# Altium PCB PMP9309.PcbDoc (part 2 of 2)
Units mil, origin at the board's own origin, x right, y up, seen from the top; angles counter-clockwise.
Board outline 7000 x 6500 mil, 4 copper layers (Top Layer, MidLayer1, MidLayer2, Bottom Layer), stack 90 mil thick; 176 components, 71 nets, 1187 pads, 29 vias.
Unrouted connection lines stored in the file: 1.
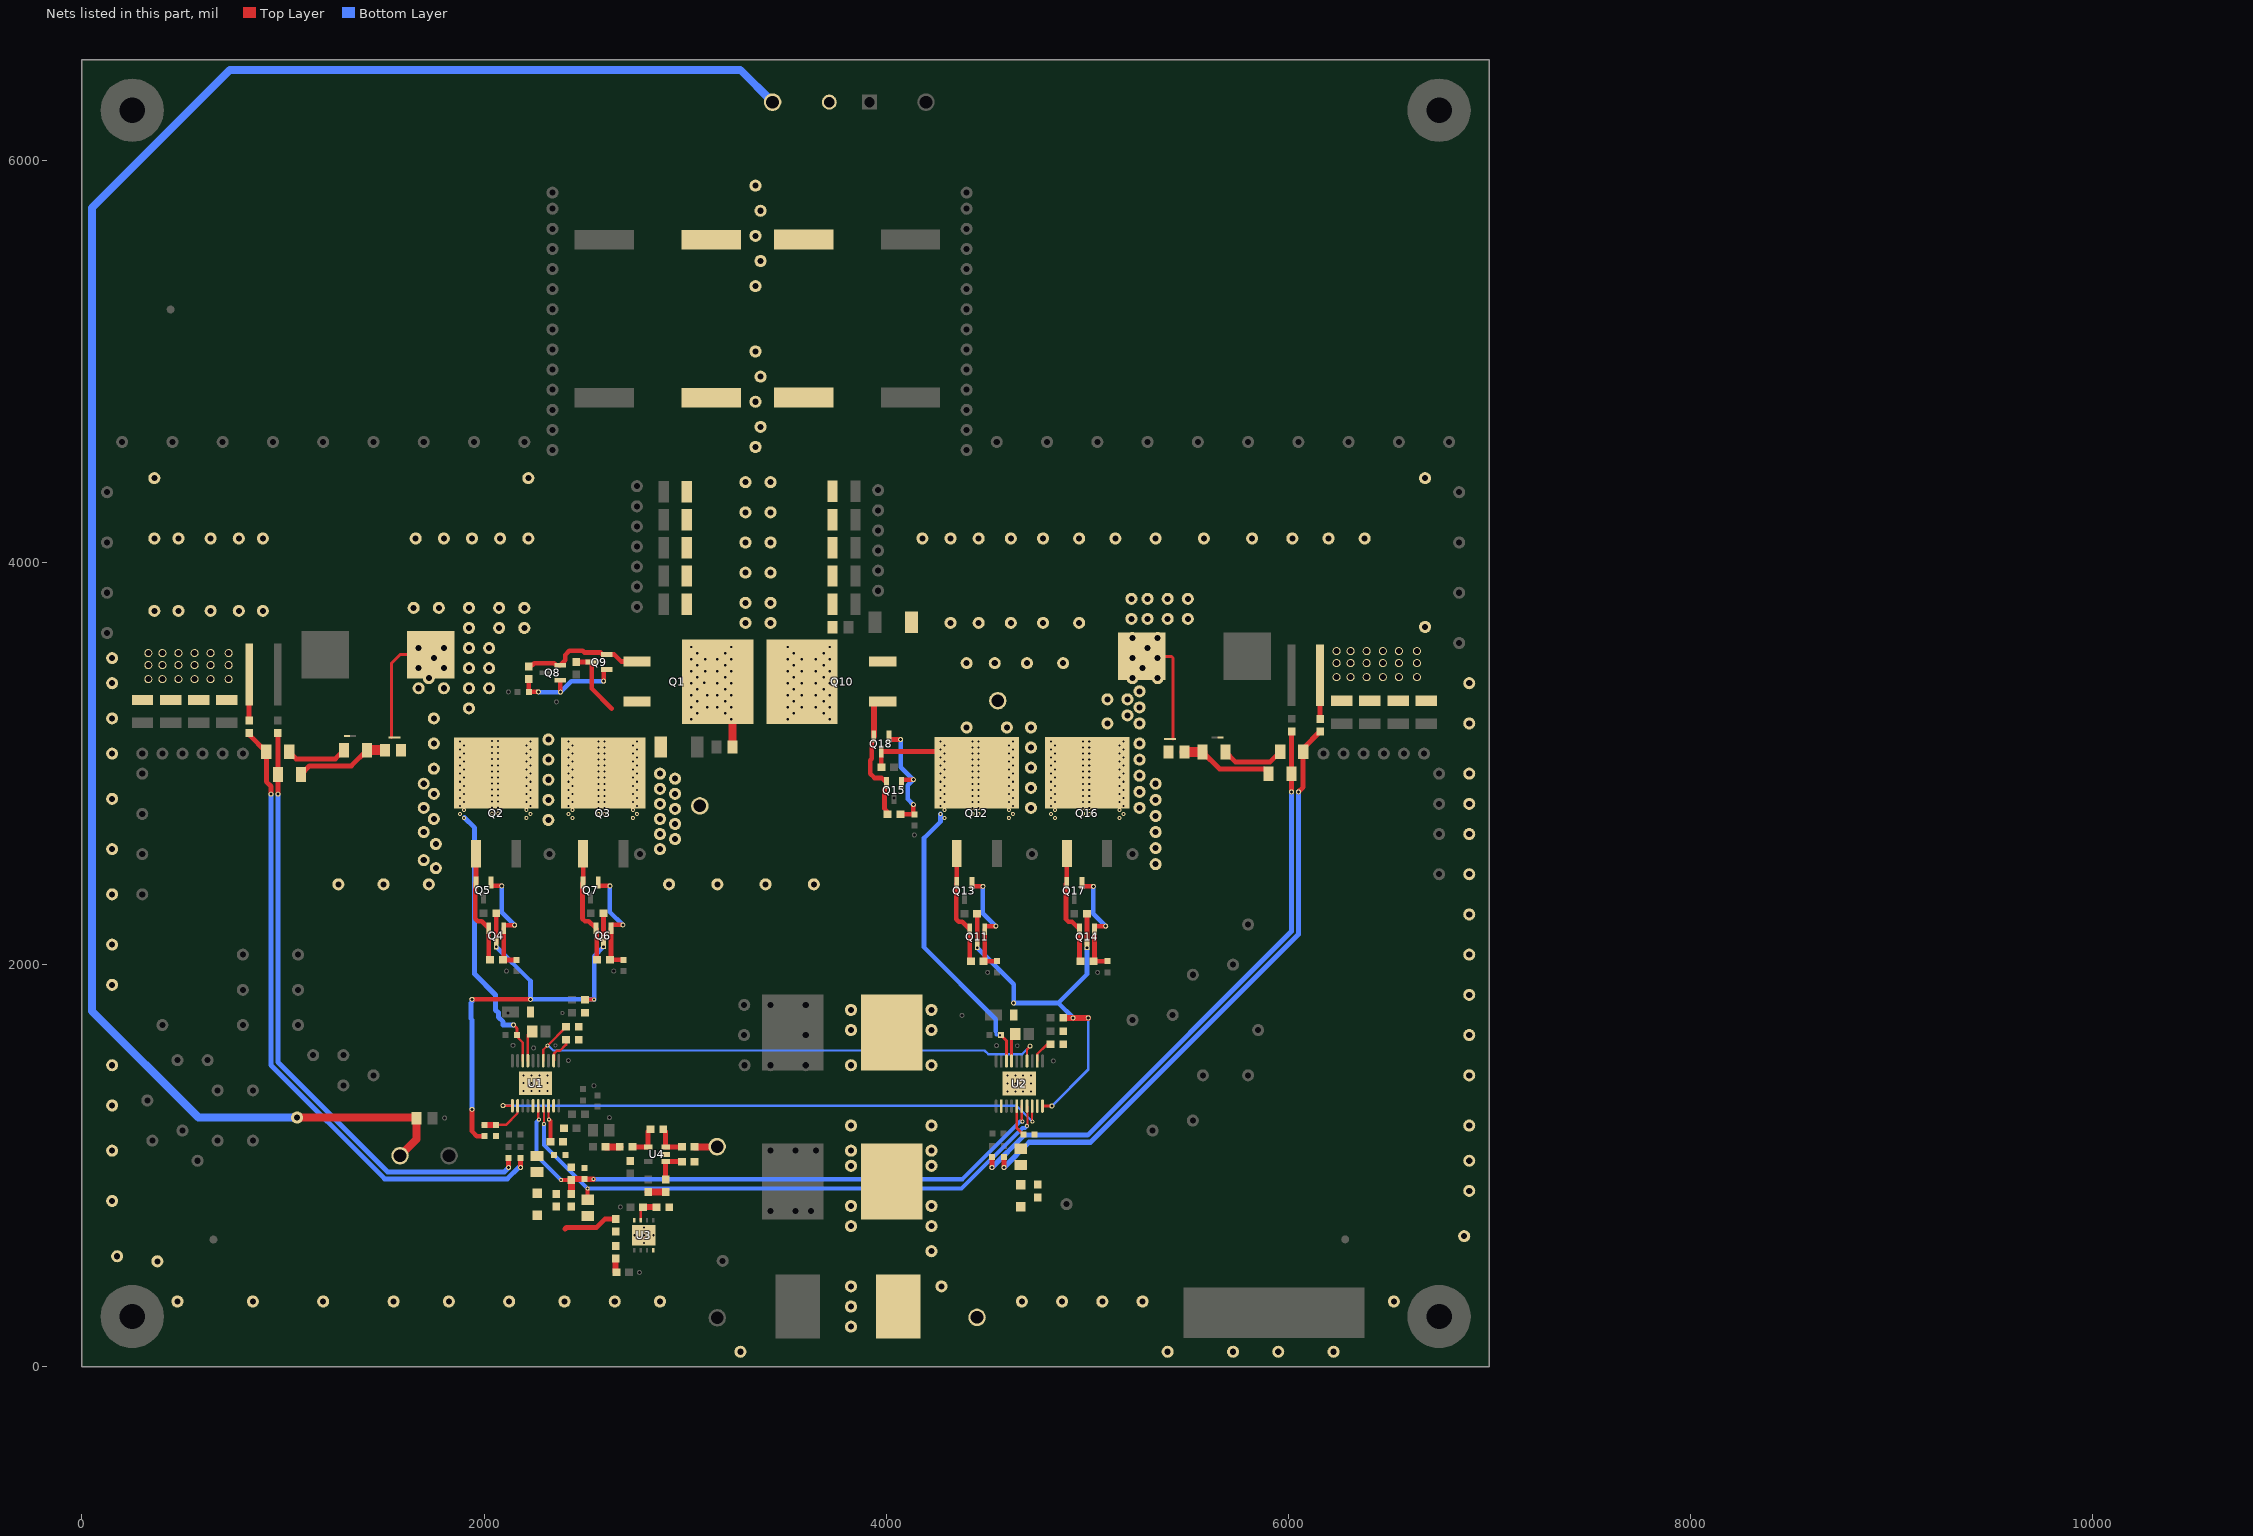
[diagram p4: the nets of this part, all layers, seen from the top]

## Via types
v1: diameter 20, hole 10, Top Layer to Bottom Layer, 29 vias

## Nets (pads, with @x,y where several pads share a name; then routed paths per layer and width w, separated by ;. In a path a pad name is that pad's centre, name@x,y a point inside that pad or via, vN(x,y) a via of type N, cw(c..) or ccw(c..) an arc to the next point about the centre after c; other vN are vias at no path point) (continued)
NetC41_1: C41.1 R39.1 R54.2 | length 467.5
  Top Layer w25: R54.2@1089.07,2946.35 1131.72,2989 1339.68,2989 C41.1@1417.68,3067
  Top Layer w50: C41.1@1417.68,3067 R39.1@1506.59,3067
NetC41_2: C41.2 NT3.1 R53.2 | length 304.5
  Top Layer w25: R53.2@1031.07,3058.35 1065.43,3024 1260.5,3024 C41.2@1303.5,3067
NetC42_1: C42.1 R55.1 R59.2 | length 462
  Top Layer w25: C42.1@5573.6,3058 5657.68,2973.92 5878,2973.92 R59.2@5901.91,2950
  Top Layer w50: R55.1@5484.68,3058 C42.1@5573.6,3058
NetC42_2: C42.2 NT5.1 R58.2 | length 313.2
  Top Layer w25: C42.2@5687.77,3058 5736.85,3008.92 5909.83,3008.92 R58.2@5959.91,3059
NetC51_1: C51.1 R41.1 | length 65
  Top Layer w30: R41.1@2654.52,472.94 C51.1@2654.52,537.94
NetNT4_1: NT4.1 R39.2
NetNT6_1: NT6.1 R55.2
NetQ1_1: Q1.1 Q8.2 Q9.2 R24.2 | length 614.8
  Top Layer w23: R24.2@2222.56,3483.94 2228.46,3489.84 2240.11,3489.84 2250.02,3499.75 2348.39,3499.75 2358.3,3489.84 Q8.2@2378.96,3489.84 2403.36,3514.24 2403.36,3540.33 2424.15,3561.12 2490.96,3561.12 2499.33,3552.75 2579.39,3552.75 2589.3,3542.84 Q9.2@2609.96,3542.84 2647.16,3542.84 2682,3508 Q1.1@2759.94,3508
NetQ2_1: Q2.1 Q4.2 Q5.2 R22.2 | length 561.3
  Top Layer w23: Q2.1@1959.6,2551.54 Q5.2@1959.6,2408.4 1956.32,2405.12 1956.32,2229.39 1968.91,2216.8 1987.89,2216.8 Q4.2@2023.6,2181.09 R22.2@2023.6,2030.59
NetQ3_1: Q3.1 Q6.2 Q7.2 R23.2 | length 567.9
  Top Layer w23: Q3.1@2492.6,2551.54 Q7.2@2492.6,2408.4 2489.32,2405.12 2489.32,2229.39 2501.91,2216.8 2521.2,2216.8 Q6.2@2556.6,2181.4 2560.69,2177.31 R23.2@2560.69,2025.82
NetQ4_1: pad.0@2088,2392 pad.0@2152,2196.69 Q4.1 Q5.1 R7.2 R22.1 | length 533.8
  Top Layer w23: Q5.1@2043,2392 pad.0@2088,2392 ; R22.1@2093.5,2023.69 R7.2@2161,2023.69 ; R22.1@2098.4,2028.59 Q4.1@2098.4,2181.09 ; Q4.1@2105,2196.69 pad.0@2152,2196.69
  Bottom Layer w23: pad.0@2088,2392 2088,2260.69 pad.0@2152,2196.69
NetQ6_1: pad.0@2626,2392 pad.0@2690,2198 Q6.1 Q7.1 R9.1 R23.1 | length 532.7
  Top Layer w23: Q7.1@2573,2392 pad.0@2626,2392 ; R23.1@2631.4,2029.91 Q6.1@2631.4,2181.4 ; R23.1@2637.31,2024 R9.1@2693,2024 ; Q6.1@2638,2198 pad.0@2690,2198
  Bottom Layer w23: pad.0@2626,2392 2626,2262 pad.0@2690,2198
NetQ8_1: pad.0@2269.56,3357.44 pad.0@2379.56,3355.44 pad.0@2594.56,3410.44 Q8.1 Q9.1 R5.1 R24.1 | length 565.4
  Top Layer w23: R5.1@2223,3357 R24.1@2223,3420.5 ; R5.1@2223.44,3357.44 pad.0@2269.56,3357.44 ; pad.0@2378.96,3356.04 Q8.1@2378.96,3415.04 ; pad.0@2594.56,3410.44 Q9.1@2594.56,3461.44
  Bottom Layer w23: pad.0@2271.56,3355.44 pad.0@2379.56,3355.44 2434.56,3410.44 pad.0@2594.56,3410.44
NetQ10_1: Q10.1 Q15.2 Q18.2 R33.2 | length 620.6
  Top Layer w23: Q18.2@3938.6,3135.4 3938.6,3114.74 3928.69,3104.83 3928.69,3023.78 3921.32,3016.41 3921.32,2949.59 3942.11,2928.8 3977.2,2928.8 Q15.2@4001.6,2904.4 4001.6,2883.74 3991.69,2873.83 3991.69,2775.46 4001.6,2765.55 4001.6,2753.91 R33.2@4007.5,2748
  Top Layer w30: Q18.2@3938.6,3135.4 Q10.1@3938.6,3297
NetQ11_1: pad.0@4481,2390 pad.0@4545,2191.98 Q11.1 Q13.1 R27.1 R30.2 | length 544.5
  Top Layer w23: Q13.1@4432,2390 pad.0@4481,2390 ; R27.1@4484.5,2017.98 R30.2@4552,2017.98 ; R27.1@4490.4,2023.89 Q11.1@4490.4,2176.39 ; Q11.1@4494,2191.98 pad.0@4545,2191.98
  Bottom Layer w23: pad.0@4481,2390 4481,2255.99 pad.0@4545,2191.98
NetQ11_2: Q11.2 Q12.1 Q13.2 R27.2 | length 567.8
  Top Layer w23: Q12.1@4351.6,2552.34 Q13.2@4351.6,2406.4 4348.32,2403.12 4348.32,2226.39 4360.91,2213.8 4378.19,2213.8 Q11.2@4415.6,2176.39 R27.2@4415.6,2023.89
NetQ14_1: pad.0@5030,2390 pad.0@5092,2192 Q14.1 Q17.1 R31.1 R32.1 | length 547.7
  Top Layer w23: Q17.1@4978,2390 pad.0@5030,2390 ; R31.1@5030.5,2018 R32.1@5100,2018 ; R31.1@5036.4,2023.91 Q14.1@5036.4,2176.4 ; Q14.1@5042,2192 pad.0@5092,2192
  Bottom Layer w23: pad.0@5030,2390 5030,2254 pad.0@5092,2192
NetQ14_2: Q14.2 Q16.1 Q17.2 R31.2 | length 568.4
  Top Layer w23: Q16.1@4898.6,2552.54 Q17.2@4898.6,2406.4 4894.32,2402.12 4894.32,2226.39 4906.91,2213.8 4924.2,2213.8 Q14.2@4961.6,2176.4 R31.2@4961.6,2023.91
NetQ15_1: pad.0@4072,3120 pad.0@4135,2796 pad.0@4135,2920 Q15.1 Q18.1 R33.1 R35.1 | length 608.1
  Top Layer w23: Q18.1@4020,3120 pad.0@4072,3120 ; R33.1@4070.5,2748 R33.1@4076.4,2753.91 ; Q15.1@4076.4,2883.74 Q15.1@4076.4,2904.4 ; Q15.1@4082,2920 pad.0@4135,2920 ; R33.1@4082.31,2748 R35.1@4140,2748 ; R35.1@4135,2753 pad.0@4135,2796
  Bottom Layer w23: pad.0@4072,3120 4072,2983 pad.0@4135,2920 4106.88,2891.88 4106.88,2824.12 pad.0@4135,2796
NetR3_2: pad.1@2182.37,991.18 pad.3@940,2848 R3.2 R51.1 R53.1 | length 3234.4
  Top Layer w25: R51.1@831.99,3143.27 R53.1@916.9,3058.35 916.9,2910.1 940,2887 pad.3@940,2848 ; pad.1@2182.37,991.18 R3.2@2182.37,1038.18
  Bottom Layer w25: pad.3@940,2848 940,1500.5 1505.5,935 2115.68,935 2171.86,991.18 pad.1@2182.37,991.18
NetR4_2: pad.0@2122.37,991.18 pad.3@975,2848 R4.2 R52.1 R54.1 | length 3064.7
  Top Layer w25: R54.1@973.99,2947.27 R52.1@973.99,3151.86 ; pad.3@975,2848 R54.1@975,2946.26 ; pad.0@2122.37,991.18 R4.2@2122.37,1038.18
  Bottom Layer w25: pad.3@975,2848 975,1515 1520,970 2101.18,970 pad.0@2122.37,991.18
NetR28_2: pad.3@4586,991.68 pad.3@6051,2860 R28.2 R56.1 R58.1 | length 3048.4
  Top Layer w25: pad.3@4586.18,991.85 R28.2@4586.18,1042.5 ; pad.3@6051,2860 6074.09,2883.09 R58.1@6074.09,3059 6074.09,3075.59 R56.1@6158,3159.5
  Bottom Layer w25: pad.3@4586,991.68 4711.32,1117 5016.5,1117 6051,2151.5 pad.3@6051,2860
NetR29_2: pad.2@4526,991.68 pad.3@6016,2860 R29.2 R57.1 R59.1 | length 3021.4
  Top Layer w25: pad.2@4526.18,991.85 R29.2@4526.18,1042.5 ; pad.3@6016,2860 R59.1@6016,2949.91 ; R59.1@6016,2950.09 R57.1@6016,3160.5
  Bottom Layer w25: pad.2@4526,991.68 4686.32,1152 5002,1152 6016,2166 pad.3@6016,2860
NetR42_1: R42.1 R43.2 U3.7 | length 120
  Top Layer w12: U3.7@2778.78,729.23 R42.1@2778.78,782.19
  Top Layer w30: R42.1@2791.02,794.43 R43.2@2858.03,794.43
NetR44_2: R44.2 R45.1 U4.1 | length 168
  Top Layer w25: R45.1@2903.52,932.61 U4.1@2903.52,1020.12 R44.2@2984.03,1020.12
NetR45_2: R45.2 R46.1 | length 87
  Top Layer w35: R46.1@2816.52,869.62 R45.2@2903.52,869.62
NetR47_1: R47.1 R50.2 U4.4 | length 171.3
  Top Layer w25: R47.1@2738.02,1094.12 U4.4@2816.52,1094.12 2816.52,1170.61 R50.2@2828.03,1182.12
NetR47_2: R47.2 R48.1 | length 70
  Top Layer w35: R48.1@2605.02,1094.12 R47.2@2675.03,1094.12
NetR49_1: R49.1 TP14.1 | length 112
  Top Layer w35: R49.1@3047.02,1094.12 TP14.1@3159.04,1094.12
NetR49_2: R49.2 R50.1 U4.3 | length 173.7
  Top Layer w25: R50.1@2891.02,1182.12 2903.52,1169.61 U4.3@2903.52,1094.12 R49.2@2984.03,1094.12
OPT1: R6.1 R8.2 U1.2 | length 226.3
  Top Layer w12: R8.2@2060.52,1203.12 2108.52,1203.12 2166.52,1261.12 2166.52,1298.07 U1.2@2166.75,1298.3
  Top Layer w30: R6.1@2001.52,1203.12 R8.2@2060.52,1203.12
RES: C19.1 pad.0@2315,1597.08 pad.0@4716,1594.68 U1.14 U2.14 | length 2729
  Top Layer w12: U1.14@2294.7,1522.71 2294.7,1576.78 pad.0@2315,1597.08 C19.1@2408.03,1690.11 ; U2.14@4700.39,1521.2 4700.39,1579.07 pad.0@4716,1594.68
  Bottom Layer w12: pad.0@2315,1597.08 2319.79,1597.08 2343.75,1573.12 4489.5,1573.12 4507.43,1555.18 4676.5,1555.18 pad.0@4716,1594.68
SGND: C19.2 C20.2 C21.2 C22.2 C49.2 C50.2 C51.2 C52.2 R8.1 R13.1 R15.1 R16.1 R17.1 R19.2 R37.1 R40.1 R43.1 R44.1 U1.9 U1.21 U2.2 U2.9 U2.21 U3.4 U3.9 U4.2
  other v1: 2794.52,615.06 2747.28,654.43 2794.52,654.43 2841.77,654.43 2794.52,693.8 4602.95,1369.63 4642.32,1369.63 4681.69,1369.63 4721.06,1369.63 2197.26,1371.13 2236.63,1371.13 2276,1371.13 2315.37,1371.13 4602.95,1409 4642.32,1409 4681.69,1409 4721.06,1409 2197.26,1410.5 2236.63,1410.5 2276,1410.5 2315.37,1410.5 4602.95,1448.37 4642.32,1448.37 4681.69,1448.37 4721.06,1448.37 2197.26,1449.87 2236.63,1449.87 2276,1449.87 2315.37,1449.87
SLOPE1: R13.2 U1.12 | length 172.8
  Top Layer w12: U1.12@2345.88,1556.06 U1.12@2345.88,1522.71 2348.58,1525.41 2348.58,1558.76 2361.99,1572.17 2377.85,1572.17 2408.03,1602.35 R13.2@2408.03,1627.12
SLOPE2: R37.2 U2.12 | length 120
  Top Layer w12: U2.12@4751.57,1521.2 4751.57,1555.25 4800,1603.68 R37.2@4817.51,1603.68
SS: C22.1 pad.0@2297.32,1207.5 pad.0@2515,886 pad.1@4700,1199 U1.7 U2.7 | length 2966.7
  Top Layer w10: U1.7@2294.7,1298.3 2297.32,1295.68 pad.0@2297.32,1210.5 ; U2.7@4700.39,1296.79 4702,1295.18 pad.1@4702,1201
  Top Layer w20: C22.1@2515,831 pad.0@2515,886
  Bottom Layer w20: pad.0@2297.32,1207.5 2297.32,1103.68 pad.0@2515,886 4374.36,886 4677.36,1189 4689.43,1189 4699.43,1199 pad.1@4700,1199
SW1: C15.1 C27.2 L1.2 NT4.2 pad.0@360,3760 pad.0@360,4420 pad.0@1275,2400 pad.0@1650,3775 pad.0@1880,3110 pad.0@2146,1701 pad.0@2230,3110 pad.0@2440,2730 pad.0@2740,2730 pad.1@360,4120 pad.1@480,3760 pad.1@1500,2400 pad.1@1775,3775 pad.1@1900,3090 pad.1@2210,3090 pad.1@2420,2750 pad.1@2760,2750 pad.2@480,4120 pad.2@640,3760 pad.2@1725,2400 pad.2@1880,3070 pad.2@1925,3775 pad.2@2230,3070 pad.2@2440,2770 pad.2@2740,2770 pad.3@640,4120 pad.3@780,3760 pad.3@1750,3100 pad.3@1900,3050 pad.3@2075,3775 pad.3@2210,3050 pad.3@2420,2790 pad.3@2760,2790 pad.4@780,4120 pad.4@900,3760 pad.4@1750,2975 pad.4@1880,3030 pad.4@2200,3775 pad.4@2230,3030 pad.4@2440,2810 pad.4@2740,2810 pad.5@900,4120 pad.5@1750,2850 pad.5@1900,3010 pad.5@1925,3675 pad.5@2210,3010 pad.5@2420,2830 pad.5@2760,2830 pad.6@1660,4120 pad.6@1750,2725 pad.6@1880,2990 pad.6@2075,3675 pad.6@2230,2990 pad.6@2440,2850 pad.6@2740,2850 pad.7@1800,4120 pad.7@1900,2970 pad.7@2200,3675 pad.7@2210,2970 pad.7@2420,2870 pad.7@2760,2870 pad.8@1880,2950 pad.8@1925,3575 pad.8@1940,4120 pad.8@2230,2950 pad.8@2440,2890 pad.8@2740,2890 pad.9@1900,2930 pad.9@1925,3475 pad.9@2080,4120 pad.9@2210,2930 pad.9@2420,2910 pad.9@2760,2910 pad.10@1880,2910 pad.10@1925,3375 pad.10@2220,4120 pad.10@2230,2910 pad.10@2440,2930 pad.10@2740,2930 pad.11@1700,2900 pad.11@1900,2890 pad.11@2025,3375 pad.11@2210,2890 pad.11@2420,2950 pad.11@2760,2950 pad.12@1700,2780 pad.12@1880,2870 pad.12@2025,3475 pad.12@2230,2870 pad.12@2440,2970 pad.12@2740,2970 pad.13@1700,2660 pad.13@1900,2850 pad.13@2025,3575 pad.13@2210,2850 pad.13@2420,2990 pad.13@2760,2990 pad.14@1800,3375 pad.14@1880,2830 pad.14@2230,2830 pad.14@2440,3010 pad.14@2740,3010 pad.15@1675,3375 pad.15@1900,2810 pad.15@2210,2810 pad.15@2420,3030 pad.15@2760,3030 pad.16@1750,3225 pad.16@1880,2790 pad.16@2230,2790 pad.16@2440,3050 pad.16@2740,3050 pad.17@1900,2770 pad.17@2210,2770 pad.17@2420,3070 pad.17@2760,3070 pad.17@2875,2950 pad.18@1880,2750 pad.18@2230,2750 pad.18@2440,3090 pad.18@2740,3090 pad.18@2875,2875 pad.19@1900,2730 pad.19@2210,2730 pad.19@2420,3110 pad.19@2760,3110 pad.19@2875,2800 pad.20@2570,3110 pad.20@2875,2725 pad.21@2600,3110 pad.21@2875,2650 pad.22@2600,3080 pad.22@2875,2575 pad.23@2570,3080 pad.23@2950,2925 pad.24@1760,2600 pad.24@2570,3050 pad.24@2950,2850 pad.25@1700,2520 pad.25@2600,3050 pad.25@2950,2775 pad.26@1760,2480 pad.26@2600,3020 pad.26@2950,2700 pad.27@2320,3120 pad.27@2570,3020 pad.27@2950,2625 pad.28@1925,3275 pad.28@2320,3020 pad.28@2570,2990 pad.29@1675,3475 pad.29@2320,2920 pad.29@2600,2990 pad.30@1675,3575 pad.30@2320,2820 pad.30@2600,2960 pad.31@1800,3575 pad.31@2320,2720 pad.31@2570,2960 pad.32@1800,3475 pad.32@2570,2930 pad.33@1750,3525 pad.33@2600,2930 pad.34@1725,3425 pad.34@2600,2900 pad.35@2570,2900 pad.36@2570,2870 pad.37@2600,2870 pad.38@2600,2840 pad.39@2570,2840 pad.40@2570,2810 pad.41 pad.42 pad.43 pad.44 pad.45 pad.46@2040,3112 pad.47@2070,3112 pad.48 pad.49 pad.50 pad.51 pad.52 pad.53 pad.54 pad.55 pad.56 pad.57 pad.58 pad.59 pad.60 pad.61 pad.62 pad.63 pad.64 pad.65 pad.66 pad.67 pad.68 pad.69 pad.70 pad.71 Q1.3 Q2.4 Q3.4 Q9.3 R1.2 TP2.1 U1.18 | length 2281.2
  Top Layer w12: C15.1@2163.52,1641.93 2192.34,1613.12 U1.18@2192.34,1522.71
  Top Layer w15: NT4.2@1540,3131 1540,3500 1582,3542 L1.2@1734.81,3542 ; pad.0@2146,1701 2163.52,1683.48 C15.1@2163.52,1651.12
  Top Layer w23: C27.2@2458.06,3505.44 Q9.3@2535.16,3505.44 2535.16,3373.84 2635,3274
  Bottom Layer w25: pad.19@1901.77,2731.77 1953,2680.54 1953,1953.59 2057,1849.59 2057,1775.12 2071,1761.12 2071,1739.7 2095,1715.7 2095,1701 pad.0@2146,1701
SW2: C44.2 C45.1 L2.1 NT6.2 pad.0@4566,1650 pad.0@5260,3100 pad.0@5260,3200 pad.0@5350,3625 pad.1@5260,3020 pad.1@5260,3280 pad.1@5350,3525 pad.2@5260,2940 pad.2@5260,3360 pad.2@5350,3425 pad.3@5200,3320 pad.3@5225,3425 pad.3@5260,2860 pad.4@5200,3240 pad.4@5225,3525 pad.4@5260,2780 pad.5@4400,3180 pad.5@5225,3625 pad.5@5340,2900 pad.6@4600,3180 pad.6@5300,3575 pad.6@5340,2820 pad.7@4720,3180 pad.7@5275,3475 pad.7@5340,2740 pad.8@4720,3080 pad.8@5340,2660 pad.9@4720,2980 pad.9@5340,2580 pad.10@4720,2880 pad.10@5340,2500 pad.11@4180,4120 pad.11@4720,2780 pad.12@4320,4120 pad.12@5100,3200 pad.13@4460,4120 pad.13@5100,3320 pad.14@4620,4120 pad.14@5220,3720 pad.15@4780,4120 pad.15@5300,3720 pad.16@4960,4120 pad.16@5400,3720 pad.17@5140,4120 pad.17@5500,3720 pad.18@5340,4120 pad.18@5500,3820 pad.19@5400,3820 pad.19@5580,4120 pad.20@5300,3820 pad.20@5820,4120 pad.21@5220,3820 pad.21@6020,4120 pad.22@6200,4120 pad.23@6380,4120 pad.32@4320,3700 pad.33@4460,3700 pad.34@4620,3700 pad.35@4780,3700 pad.36@4960,3700 pad.37@4400,3500 pad.38@4540,3500 pad.39@4700,3500 pad.40@4880,3500 pad.46@6680,4420 pad.47@6680,3680 pad.72 pad.73 pad.74 pad.75 pad.76 pad.77 pad.78 pad.79 pad.80 pad.81 pad.82 pad.83 pad.84 pad.85 pad.86 pad.87 pad.88 pad.89 pad.90 pad.91 pad.92 pad.93 pad.94 pad.95 pad.96 pad.97 pad.98 pad.99 pad.100 pad.101 pad.102 pad.103 pad.104 pad.105 pad.106 pad.107 pad.108 pad.109 pad.110 pad.111 pad.112 pad.113 pad.114 pad.115 pad.116 pad.117 pad.118 pad.119 pad.120 pad.121 pad.122 pad.123 pad.124 pad.125 pad.126 pad.127 pad.128 pad.129 pad.130 pad.131 pad.132 pad.133 pad.134 pad.135 pad.136 pad.137 pad.138 pad.139 pad.140 pad.141 pad.142 pad.143 pad.144 pad.145 pad.146 pad.147 pad.148 pad.149 pad.150 pad.151 pad.152 pad.153 pad.154 pad.155 pad.156 pad.157 pad.158 pad.159 pad.160 pad.161 pad.162 pad.163 pad.164 pad.165 pad.166 pad.167 pad.168 pad.169 pad.170 pad.171 pad.172 pad.173 pad.174 pad.175 pad.176 pad.177 pad.178 pad.179 pad.180 pad.181 pad.182 pad.183 pad.184 pad.185 pad.186 pad.187 pad.188 pad.189 pad.190 pad.191 pad.192 pad.193 pad.194 pad.195 pad.196 pad.197 pad.198 pad.199 pad.200 pad.201 pad.202 pad.203 Q10.3 Q12.4 Q16.4 Q18.3 R25.2 TP9.1 U2.18 | length 2599.5
  Top Layer w14: C45.1@4570,1649.68 4598.03,1621.66 U2.18@4598.03,1521.2
  Top Layer w15: L2.1@5271.19,3533 5420,3533 5427,3526 NT6.2@5427,3122
  Top Layer w23: C44.2@3976,2983.5 Q18.3@3976,3060.6 4344.91,3060.6 Q12.4@4451,2954.51
  Bottom Layer w14: 4546.47,1668.1 4546.47,1650 pad.0@4566,1650
  Bottom Layer w23: pad.93@4270,2750 4270,2712 4188,2630 4188,2086.88 4545.57,1729.31 4545.57,1669
SYNC/RT1: pad.0@2322.32,1229.5 R16.2 U1.8 | length 181.3
  Top Layer w12: pad.0@2320.29,1230.53 U1.8@2320.29,1298.3
  Top Layer w20: pad.0@2322.32,1229.5 2329.5,1222.31 R16.2@2329.5,1119
SYNCOUT1: pad.0@2094.52,1299.12 pad.2@4727,1219 U1.1 U2.8 | length 2788.3
  Top Layer w10: pad.2@4725.98,1220.02 U2.8@4725.98,1296.79
  Top Layer w12: pad.0@2095.34,1298.3 U1.1@2141.16,1298.3
  Bottom Layer w12: pad.0@2094.52,1299.12 4646.88,1299.12 pad.2@4727,1219
UVLO: C20.1 pad.0@2272.32,1229.5 pad.0@2383.52,929.12 pad.0@2544,933 pad.0@4677,1219 R11.1 R15.2 U1.6 U2.6 | length 2977.8
  Top Layer w12: pad.0@2269.11,1229.71 U1.6@2269.11,1298.3 ; pad.0@4674.8,1221.2 U2.6@4674.8,1296.79
  Top Layer w20: pad.0@2383.52,929.12 R15.2@2433.56,929.12
  Top Layer w25: C20.1@2499.18,933 pad.0@2544,933
  Top Layer w30: R15.2@2437.56,933.12 C20.1@2499.06,933.12
  Top Layer w35: R11.1@2434.06,859.61 R15.2@2434.06,929.62
  Bottom Layer w20: pad.0@2272.32,1229.5 2261,1218.19 2261,1051.64 pad.0@2383.52,929.12 ; pad.0@2544,933 4378.93,933 4664.93,1219 pad.0@4677,1219
VCC1: C17.2 C25.1 C26.1 D1.2 pad.0@1940,1281 pad.0@1940,1828 pad.0@2061,2089 pad.0@2231,1828 pad.0@2547.52,1826.12 pad.1@2594,2089 Q4.3 Q6.3 R6.2 R14.2 U1.17 | length 2426.7
  Top Layer w12: U1.17@2217.93,1522.71 C17.2@2217.93,1651.12
  Top Layer w20: R14.2@2501.02,1826.12 pad.0@2547.52,1826.12
  Top Layer w23: pad.0@1940,1281 1940,1171 1963.88,1147.12 R6.2@2001.52,1147.12 ; pad.0@1940.18,1828.18 2230.82,1828.18 pad.0@2231,1828 ; Q4.3@2061,2106.28 C25.1@2061,2256.5 ; Q6.3@2594,2106.6 C26.1@2594,2256.5
  Bottom Layer w23: pad.0@1940,1281 1940,1726.24 1935,1731.24 1935,1810.76 1940,1815.76 pad.0@1940,1828 ; pad.0@2061,2089 2231,1919 pad.0@2231,1828 pad.0@2545.64,1828 ; pad.0@2547.52,1826.12 2547.52,2042.52 pad.1@2594,2089
VCC2: C29.1 C43.1 C47.2 D3.2 pad.0@4634,1809.68 pad.0@4824,1297 pad.0@4930,1735.68 pad.0@5005,1736 pad.2@4453,2084 pad.3@4999,2084 Q11.3 Q14.3 R38.2 U2.10 U2.17 | length 2103.6
  Top Layer w14: U2.17@4623.62,1521.2 C47.2@4623.62,1626.76 ; U2.10@4777.16,1296.79 pad.0@4823.79,1296.79
  Top Layer w23: Q11.3@4453,2101.58 C29.1@4453,2253.5 ; Q14.3@4999,2101.6 C43.1@4999,2253.5
  Top Layer w30: R38.2@4880.5,1735.68 pad.0@4930,1735.68 pad.0@5004.68,1735.68
  Bottom Layer w14: pad.0@4824,1297 5005,1478 pad.0@5005,1736
  Bottom Layer w23: pad.2@4453,2084 4634,1903 pad.0@4634,1809.68 4856,1809.68 ; pad.0@4930,1735.68 4856,1809.68 ; pad.3@4999,2084 4999,1952.68 4856,1809.68
VIN1: C21.1 R12.1 U1.5
VIN2: C49.1 R36.1 U2.5 | length 155.4
  Top Layer w12: 4649.2,1207.48 U2.5@4649.21,1296.79
  Top Layer w14: 4649.2,1207.48 4649.2,1187.8 C49.1@4682,1155
VIN+: C3.1 C4.1 C5.1 C6.1 C7.1 C31.1 C32.1 C33.1 C34.1 C35.1 C50.1 D2.2 D4.2 J1.1 pad.0@150,3525 pad.0@330,3550 pad.0@4225,1200 pad.0@6240,3560 pad.0@6900,1650 pad.0@6900,2250 pad.0@6900,3400 pad.1@150,3400 pad.1@400,3550 pad.1@4225,1075 pad.1@6310,3560 pad.1@6900,1450 pad.1@6900,2050 pad.1@6900,3200 pad.2@150,3225 pad.2@480,3550 pad.2@4225,1000 pad.2@6390,3560 pad.2@6900,1850 pad.2@6900,2800 pad.2@6900,2950 pad.3@150,3050 pad.3@560,3550 pad.3@4225,800 pad.3@6470,3560 pad.3@6900,2650 pad.4@150,2825 pad.4@640,3550 pad.4@4225,700 pad.4@4225,1775 pad.4@6550,3560 pad.4@6900,2450 pad.5@150,2575 pad.5@730,3550 pad.5@4225,575 pad.5@4225,1675 pad.5@6640,3560 pad.6@150,2350 pad.6@330,3490 pad.6@4225,1500 pad.6@4275,400 pad.6@6240,3500 pad.7@150,2100 pad.7@400,3490 pad.7@6310,3500 pad.7@6900,1200 pad.8@150,1900 pad.8@480,3490 pad.8@6390,3500 pad.8@6900,1025 pad.9@150,1500 pad.9@560,3490 pad.9@6470,3500 pad.9@6900,875 pad.10@150,1300 pad.10@640,3490 pad.10@6550,3500 pad.10@6875,650 pad.11@150,1075 pad.11@730,3490 pad.11@6525,325 pad.11@6640,3500 pad.12@150,825 pad.12@330,3420 pad.12@6240,3430 pad.13@175,550 pad.13@400,3420 pad.13@6310,3430 pad.14@475,325 pad.14@480,3420 pad.14@6390,3430 pad.15@375,525 pad.15@560,3420 pad.15@6470,3430 pad.16@640,3420 pad.16@850,325 pad.16@6550,3430 pad.17@730,3420 pad.17@1200,325 pad.17@6640,3430 pad.18@1550,325 pad.19@1825,325 pad.20@2125,325 pad.21@2400,325 pad.22@2650,325 pad.22@4675,325 pad.23@2875,325 pad.23@4875,325 pad.24@5075,325 pad.24@5400,75 pad.25@5275,325 pad.25@5725,75 pad.26@3825,1775 pad.26@5950,75 pad.27@3825,1675 pad.27@6225,75 pad.28@3825,1500 pad.29@3825,1200 pad.30@3825,1075 pad.31@3825,1000 pad.32@3825,800 pad.33@3825,700 pad.34@3825,400 pad.35@3825,300 pad.36@3825,200 pad.37@3275,75 R2.2 R10.2 R11.2 R26.2 R34.2 R51.2 R56.2 TP1.1 U3.8 | length 717.9
  Top Layer w25: R51.2@831.99,3214.85 R2.2@831.99,3443.22 ; 2403,686 2410.5,693.5 2559.96,693.5 2602.39,735.93 C50.1@2654.52,735.93 ; R56.2@6158,3222.5 R26.2@6158,3439.87
VIN+X1: D2.1 R10.1 R12.2
VIN+X2: D4.1 R34.1 R36.2
VOUT: C1.2 C2.1 C8.1 C9.1 C10.1 C11.1 C12.1 C13.1 C14.1 C28.2 C30.1 C36.1 C37.1 C38.1 C39.1 C40.1 J2.2 pad.0@1070,1240 pad.0@3096.08,3402.37 pad.0@3300,3700 pad.1@3425,3700 pad.2@3425,3800 pad.3@3300,3800 pad.4@3300,3950 pad.5@3425,3950 pad.6@3425,4100 pad.7@3300,4100 pad.8@3300,4250 pad.9@3425,4250 pad.10@3425,4400 pad.11@3300,4400 pad.12@3350,4575 pad.13@3375,4675 pad.14@3350,4800 pad.15@3375,4925 pad.16@3350,5050 pad.17@3350,5375 pad.18@3375,5500 pad.19@3350,5625 pad.20@3375,5750 pad.21@3350,5875 pad.204 pad.205 pad.206 pad.207 pad.208 pad.209 pad.210 pad.211 pad.212 pad.213 pad.214 pad.215 pad.216 pad.217 pad.218 pad.219 pad.220 pad.221 pad.222 pad.223 pad.224 pad.225 pad.226 pad.227 pad.228 pad.229 pad.230 pad.231 pad.232 pad.233 pad.234 pad.235 pad.236 pad.237 pad.238 pad.239 pad.240 pad.241 pad.242 pad.243 pad.244 pad.245 pad.246 pad.247 pad.248 pad.249 pad.250 pad.251 pad.252 pad.253 pad.254 pad.255 pad.256 pad.257 pad.259 pad.260 pad.261 pad.262 pad.263 pad.264 pad.265 pad.266 pad.267 pad.268 pad.269 pad.270 pad.271 pad.272 pad.273 pad.274 pad.275 Q1.4 Q10.4 R21.1 TP3.1 TP8.1 | length 10035.3
  Top Layer w40: pad.0@1070,1240 R21.1@1661,1240 ; TP8.1@1582,1050 1664,1132 R21.1@1664,1237 ; C1.2@3235,3083 pad.238@3235,3334.51
  Bottom Layer w40: pad.0@1070,1240 579,1240 49,1770 49,5764.06 735.94,6451 3274,6451 TP3.1@3435,6290
pads on no net: FID1.1 FID2.1 FID3.1 H1.1 H2.1 H3.1 H4.1 H9.0 H10.0 H11.0 H12.0 Logo1.0 U2.1 U3.2 U3.3 U3.5 U3.6

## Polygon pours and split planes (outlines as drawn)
SW1 on MidLayer1 "MidLayer1-SW1" (solid, remove dead copper, pour order 41): 230,4500 2300,4500 2300,3558 2074,3558 2074,3237 2076,3239 2494,3239 2585,3288 2708,3354 2710,3449 2900,3449 2900,3136 2910,3136 2910,3040 2950,3000 3700,3000 3700,2308 2818,2308 2818,2660 1825,2660 1825,2309 1810,2309 1809,2310 1200,2310 1200,2800 1211,2804 1221,2808 1481,2905 1700,2987 1700,3210 1612,3298 1612,3684 230,3684
SW2 on MidLayer1 "MidLayer1-SW2" (solid, remove dead copper, pour order 49): 4350,4500 6740,4500 6740,3620.39 6059.86,3620.39 6060,3620.53 6060,3695 5646,3695 5646,3670 5400,3670 5400,3375 5299,3375 5299,2999 5591,2844 5881,2764 5881,2424 5880,2423 5268,2423 5268,2689 5267,2690 4240,2690 4240,3180 4050,3370 3840,3370 3840,3600 4100,3600 4100,4400 4250,4400
VOUT on MidLayer1 "MidLayer1-Vout" (solid, remove dead copper, pour order 63): 0,4051 229,4051 230,4500 2300,4500 2300,3558 2984,3558 2984,3198 3759,3198 3759,3600 4100,3600 4100,4500 6741,4500 6741,4047 7000,4047 7000,6500 0,6500
VIN+ on MidLayer1 "MidLayer1-Vin+" (solid, remove dead copper, pour order 65): 0,4050 230,4050 230,4046 230,3597 241,3597 790,3597 790,3582 790,2914 904,2800 1200,2800 1200,2310.41 1200.41,2310 1223,2310 5772,2310 5883,2421 5883,2701 5985,2701 6204,2920 6204,2951 6204,3620 6210,3620 6739.61,3620 6740,3620.39 6740,4047 6767,4047 7000,4047 7000,4043 7000,0 1,0 0,1 0,4050
GND on MidLayer2 "MidLayer2-GND" (solid, remove dead copper, pour order 67): 0,6500 7000,6500 7000,0 0,0 0,6500
SW1 on Bottom Layer "Bottom Layer-SW1" (solid, remove dead copper, pour order 45): 230,4500 2300,4500 2300,3558 2299,3557 2077,3557 2075,3557 2074,3558 2074,3237 2622,3237 2730,3345 2729,3346 2729,3449 2900,3449 2900,3136 2910,3136 2910,3116 2910,3040 2950,3000 3700,3000 3700,2308 2818,2308 2818,2660 1825,2660 1825,2309 1201,2309 1200,2310 1200,2800 1513,2800 1700,2987 1700,3203 1700,3210 1612,3298 1612,3684 230.11,3684 230,3684.11 230,4500
SW2 on Bottom Layer "Bottom Layer-SW2" (solid, remove dead copper, pour order 53): 4350,4500 6740,4500 6740,3620.53 6060,3620.53 6060,3695 5645,3695 5645,3670 5400,3670 5400,3375 5299,3375 5299,2999 5591,2844 5881,2764 5881,2424 5880,2423 5268,2423 5268,2689 5267,2690 4240,2690 4240,3180 4050,3370 3840,3370 3840,3600 4100,3600 4100,4400 4250,4400
GND on Bottom Layer "Bottom Layer-GND" (solid, remove dead copper, pour order 70): 0,6500 7000,6500 7000,0 0,0 0,6500
SW1 on Top Layer "Top Layer-SW1" (solid, remove dead copper, pour order 39): 230,3684 230,4500 2300,4500 2300,3558 2074,3558 2074,3237 2284,3236 2494,3239 2708,3354 2710,3449 2900,3450 2900,3050 2950,3000 3700,3000 3700,2308 2818,2308 2818,2660 1825,2660 1825,2309 1200,2310 1200,2800 1700,2987 1700,3203 1612,3298 1612,3684
GND on Top Layer "Top Layer-GND" (solid, remove dead copper, pour order 61): 0,6500 7000,6500 7000,0 0,0 0,6500
SW2 on Top Layer "Top Layer-SW2" (solid, remove dead copper, pour order 47): 4050,3370 3840,3370 3840,3600 4100,3600 4100,4400 4250,4400 4350,4500 6740,4500 6740,3620 6050,3620 6049,3670 5400,3670 5400,3375 5299,3375 5299,2999 5591,2844 5881,2764 5880,2690 5880,2423 5268,2423 5267,2690 4240,2690 4240,3180
VOUT on Top Layer "Top Layer-Vout" (solid, remove dead copper, pour order 29): 2984,3198 2987,3198 3759,3198 3759,3202 3759,3323 3759,6500 3733,6500 2984,6500 2984,6476 2984,6424 2984,6378 2984,3198
VIN+ on Top Layer "Top Layer-Vin+c" (solid, remove dead copper, pour order 55): 230,3597 290,3597 290,3292 250,3292 250,3265 250,3239 250,864 698,416 735,416 3601,416 3688,503 3688,524 3688,1851 3711,1851 4270,1851 4270,1812 4270,524 4379,415 4407,415 6305,415 6750,860 6750,895 6750,3288 6700,3288 6700,3600 6724,3600 7000,3600 7000,3595 7000,0 0,0 0,3597 230,3597
VIN+X2 on Top Layer "Top Layer-Vin+X2" (solid, remove dead copper, pour order 4): 4637,1025.68 4637,1029.68 4639,1029.68 4775,1029.68 4775,1019.68 4775,885.68 4740,885.68 4637,885.68 4637,889.68 4637,1025.68
VCC1 on Top Layer "Top Layer-VCC1" (solid, remove dead copper, pour order 11): 2214,1790 2214,1841 2250,1841 2250,1823 2250,1700 2264,1700 2264,1638 2214,1638 2214,1790
VIN+X1 on Top Layer "Top Layer-Vin+X1" (solid, remove dead copper, pour order 2): 2231.52,993.12 2234.52,993.12 2377.52,993.12 2377.52,839.12 2361.52,839.12 2231.52,839.12 2231.52,993.12
VIN2 on Top Layer "Top Layer-Vin2" (solid, remove dead copper, pour order 15): 4635,1283.68 4635,1285.68 4665,1285.68 4665,1274.68 4665,1225.68 4665,1221.68 4665,1216.68 4697,1184.68 4697,1171.68 4697,1163.68 4701,1159.68 4701,1134.68 4701,1059.68 4635,1059.68 4635,1064.68 4635,1283.68
+5V on Top Layer "Top Layer-+5V" (solid, remove dead copper, pour order 17): 2837.52,913.12 2749.52,913.12 2749.52,774.12 2706.52,774.12 2706.52,981.12 2795.52,981.12 2795.52,1033.12 2837.52,1033.12
FB on Top Layer "Top Layer-FB" (solid, remove dead copper, pour order 19): 2364.52,1332.12 2517.52,1332.12 2517.52,1305.12 2457.52,1305.12 2457.52,1251.12 2499.52,1209.12 2561.52,1209.12 2561.52,1075.12 2517.52,1075.12 2517.52,1168.12 2440.52,1168.12 2440.52,1237.12 2418.52,1237.12 2418.52,1265.12 2364.52,1265.12
BST2 on Top Layer "Top Layer-BST2" (solid, remove dead copper, pour order 23): 4490,1775.68 4490,1776.68 4493,1776.68 4577,1776.68 4577,1721.68 4529,1721.68 4529,1691.68 4529,1595.68 4547,1577.68 4547,1554.68 4547,1493.68 4490,1493.68 4490,1506.68 4490,1775.68
VCC2 on Top Layer "Top Layer-VCC2" (solid, remove dead copper, pour order 21): 4667,1623.68 4667,1625.68 4667,1684.68 4652,1684.68 4652,1823.68 4616,1823.68 4616,1804.68 4616,1623.68 4667,1623.68
VIN+ on Top Layer "Top Layer-Vin+" (solid, remove dead copper, pour order 25): 2738,718 2752,718 2752,756 2705,756 2635,756 2635,718 2675,718 2699,718 2738,718
VIN1 on Top Layer "Top Layer-Vin1" (solid, remove dead copper, pour order 8): 2226.52,1300.12 2260.52,1300.12 2260.52,1223.12 2294,1190 2294,1077 2365,1077 2365,1021 2227,1021
COMP on Top Layer "Top Layer-COMP" (solid, remove dead copper, pour order 27): 2478,1387 2478,1411 2505,1411 2551,1411 2580,1382 2580,1367 2580,1335 2550,1335 2539,1335 2508,1366 2478,1366 2478,1387
VIN+ on Top Layer "Top Layer-Vin+a" (solid, remove dead copper, pour order 33): 851,3292 842,3292 231,3292 230,3293 230,3309 230,3597 236,3597 851,3597 851,3292
VIN+ on Top Layer "Top Layer-Vin+b" (solid, remove dead copper, pour order 37): 6139,3289 6139,3300 6139,3523 6139,3600 6148,3600 6740,3600 6740,3589 6740,3289 6734,3289 6139,3289
BST1 on Top Layer "Top Layer-BST1" (solid, remove dead copper, pour order 13): 2174.52,1792.12 2175,1730 2148,1730 2147.52,1496.12 2083.52,1496.12 2083.52,1792.12
LIN1 on Top Layer "Top Layer-Lin1" (solid, remove dead copper, pour order 31): 1331,3341 1047,3341 996,3290 955,3290 955,3662 1331,3662
LIN2 on Top Layer "Top Layer-Lin2" (solid, remove dead copper, pour order 35): 5670,3670 5670,3348 5935,3348 5996,3287 6035,3287 6035,3670
SGND on Top Layer "Top Layer-SNGD2" (solid, remove dead copper, pour order 59): 4390,1770 4623,1770 4623,1490 4797,1490 4797,1770 4970,1770 4970,740 4390,740
SGND on Top Layer "Top Layer-SGND1" (solid, remove dead copper, pour order 57): 1841,1870 2225,1870 2225,1480 2391,1480 2391,1870 3306,1869 3306,387 1841,387

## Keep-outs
Keep-Out Layer:
  the board outline again, w10
  text ".Layer_Name" at 577,-858.49 h60

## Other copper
Top Layer:
  rectangle net NetNT6_1: 5380,3075 5395,3126
  rectangle net NetC42_2: 5662.92,3079.24 5678.68,3132
  rectangle net NetC41_2: 1303,3091 1327,3140
  rectangle net NetNT4_1: 1572,3086 1587,3136
  rectangle net VIN+: 2216,348 2452,815
  rectangle net VIN+: 4204,770 4772,861
  text ".CopyrightYear" at 532,90 h60
  text "TI" at 808,90 h60
  text "©" at 415,86.48 h105
  text ".Layer_Name" at 577,-858.49 h60
Bottom Layer:
  text ".VersionControl_RevNumber" at 6002,605.5 h60
  text "SVN:" at 6175,525 h60
  text "UL94V-0" at 5300,475 h60
  text "MADE IN U.S." at 1250,86.5 h60
  text ".Layer_Name" at 577,-858.49 h60

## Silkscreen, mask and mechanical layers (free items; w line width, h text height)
Top Overlay:
  text "PMP9309 REV3C" at 716,6143 h100
  text ".Layer_Name" at 577,-858.49 h60
Bottom Overlay:
  rectangle: 638,150 938,250
  text ".PCB_Rev" at 1108,160 h60
  text ".PRJ_Number" at 1604,160 h60
  text "-" at 1003,149.5 h60
  text ".Layer_Name" at 577,-858.49 h60
Top Paste:
  text ".Layer_Name" at 577,-858.49 h60
Bottom Paste:
  text ".Layer_Name" at 577,-858.49 h60
Top Solder:
  text ".Layer_Name" at 577,-858.49 h60
  text ".Layer_Name" at 577,-858.49 h60
Bottom Solder:
  text ".Layer_Name" at 577,-858.49 h60
Drill Guide:
  text ".Layer_Name" at 577,-858.49 h60
M1 Board Outline:
  the board outline again, w10
  text ".Layer_Name" at 577,-858.49 h60
M2 Board Dimensions:
  rectangle: -0.5,-285.5 124.5,-160.5
  rectangle: 124.5,-410.5 499.5,-285.5
  lines w7: -0.5,-285.5 999.5,-285.5 ; 124.5,-410.5 124.5,-160.5 ; 249.5,-410.5 249.5,-160.5 ; 499.5,-410.5 499.5,-160.5 ; 749.5,-410.5 749.5,-160.5 ; -0.5,-410.5 999.5,-410.5 999.5,-160.5 -0.5,-160.5 -0.5,-410.5
  lines w10: -0.5,-475.5 -0.5,-455.5 ; 59.5,-485.5 -0.5,-465.5 ; 59.5,-445.5 -0.5,-465.5 ; 223.58,-465.5 -0.5,-465.5 ; 775.42,-465.5 999.5,-465.5 ; 939.5,-485.5 999.5,-465.5 ; 939.5,-445.5 999.5,-465.5 ; 999.5,-475.5 999.5,-455.5
  text "1000 (mil)" at 233.58,-501.49 h60
  text ".Layer_Name" at 577,-858.49 h60
M3 3D STEP Top:
  text ".Layer_Name" at 577,-858.49 h60
M4 3D STEP Bottom:
  text ".Layer_Name" at 577,-858.49 h60
M5 Assembly Top:
  lines w10: -292,-930.17 6308,-930.17 ; -292,-726.83 6310,-726.83 ; -292,-523.5 -292,-1133.5 3713,-1133.5 6310,-1133.5 6310,-523.5 -291.5,-523.5 -291.5,-1133.5 1284,-1133.5 ; 2173,-1133.5 2173,-523.5 ; 3440,-726.83 3440,-523.5 ; 4280,-726.83 4280,-523.5 ; 4902,-1140 4902,-937.17
  text "COMPONENTS MARKED 'DNP' SHOULD NOT BE POPULATED." at 1153.5,-318.5 h60
  text "ASSEMBLY VARIANT:" at 1153,-434 h60
  text ".VariantName" at 2189,-434 h60
  text "PCB VIEWED FROM TOP SIDE" at -228.5,-655.67 h60
  text "BOARD #:" at 2248,-655.67 h60
  text ".PRJ_Number" at 2793.5,-655.67 h60
  text "REV:" at 3875,-655.67 h60
  text ".PCB_Rev" at 4166.5,-655.67 h60
  text "SVN REV:" at 4476,-655.67 h60
  text ".VersionControl_RevNumber" at 4982,-655.67 h60
  text "IGNORE ->" at -228.5,-858.49 h60
  text "PLOT NAME =" at -228.5,-1064.34 h60
  text ".plot_File_Name" at 577,-1064.34 h60
  text "GENERATED    :" at 2250,-1064.34 h60
  text ".Print_Date" at 3119.5,-1064.34 h60
  text ".Print_Time" at 3848.5,-1064.34 h60
  text "TEXAS INSTRUMENTS" at 5113,-1064.34 h60
M6 Assembly Bottom:
  lines w10: -292.5,-727.33 6309.5,-727.33 ; -290.5,-930.67 6309.5,-930.67 ; 1115.5,-1140.5 1115.5,-937.67 ; 1737.5,-727.33 1737.5,-524 ; 2577.5,-727.33 2577.5,-524 ; 3844.5,-1134 3844.5,-524 ; 4733.5,-1134 6309,-1134 6309,-524 -292.5,-524 -292.5,-1134 2304.5,-1134 6309.5,-1134 6309.5,-524
  text "COMPONENTS MARKED 'DNP' SHOULD NOT BE POPULATED." at 6102,-318 h60
  text ".VariantName" at 5058,-434 h60
  text "ASSEMBLY VARIANT:" at 6097,-434 h60
  text ".VersionControl_RevNumber" at 1035.5,-656.17 h60
  text "SVN REV:" at 1541.5,-656.17 h60
  text ".PCB_Rev" at 2088,-656.17 h60
  text "REV:" at 2379.5,-656.17 h60
  text ".PRJ_Number" at 3461,-656.17 h60
  text "BOARD #:" at 4006.5,-656.17 h60
  text "PCB VIEWED FROM BOTTOM SIDE" at 6246,-656.17 h60
  text "IGNORE ->" at 2547.85,-858.49 h60
  text "TEXAS INSTRUMENTS" at 904.5,-1064.84 h60
  text ".Print_Time" at 2169,-1064.84 h60
  text ".Print_Date" at 2898,-1064.84 h60
  text "GENERATED    :" at 3767.5,-1064.84 h60
  text ".plot_File_Name" at 5440.5,-1064.84 h60
  text "PLOT NAME =" at 6246,-1064.84 h60
M9 Title Sheet:
  drawing of 57 lines, arcs and shapes, not listed
  text "1" at 739.84,8036.5 h70
  text "2" at 3235.5,8036.5 h70
  text "3" at 5724.84,8036.5 h70
  text "4" at 8231.51,8036.5 h70
  text "5" at 10730.5,8036.5 h70
  text "6" at 13235.5,8036.5 h70
  text "A" at -416.5,6893.5 h70
  text "A" at 14383.5,6893.5 h70
  text "B" at -416.5,4513.5 h70
  text "B" at 14383.5,4513.5 h70
  text "C" at -416.5,2138.5 h70
  text "C" at 14383.5,2138.5 h70
  text "PROJECT TITLE:" at 11343.5,277.5 h45
  text ".PRJ_Title" at 11393.5,144.17 h70
  text "DESIGNED FOR:" at 11343.5,-23.5 h45
  text ".PRJ_Customer" at 11393.5,-163.5 h70
  text "D" at -416.5,-231.5 h70
  text "D" at 14383.5,-231.5 h70
  text "FILE NAME:" at 11343.5,-323.5 h45
  text ".PCB_File_Name_No_Path" at 11393.5,-443.5 h70
  text "Texas Instruments (TI) and/or its licensors do not warrant the accuracy or completeness of this specification" at 6374,-605.34 h45
  text "ENGINEER:" at 11343.5,-613.5 h45
  text "LAYOUT BY:" at 12848.5,-613.5 h45
  text "or any information contained therein. TI and/or its licensors do not warrant that this design will meet" at 6329.01,-718 h45
  text ".PRJ_Engineer" at 11393.5,-768.49 h70
  text ".PCB_Layout" at 12899,-768.49 h70
  text "the specifications, will be suitable for your application or fit for any particular purpose, or will operate in" at 6329.01,-830.67 h45
  text ".Layer_Name" at 577,-858.49 h60
  text "ALTIUM DESIGNER VERSION:" at 12848.5,-923.5 h45
  text "an implementation. TI and/or its licensors do not warrant that the design is production worthy. You should" at 6329.01,-943.33 h45
  text "completely validate and test your design implementation to confirm the system functionality for your application." at 6374,-1056 h45
  text ".print_Scale" at 11393.5,-1056.83 h70
  text ".Application_BuildNumber" at 12899,-1056.83 h70
  text "1" at 739.84,-1263.5 h70
  text "2" at 3235.5,-1263.5 h70
  text "3" at 5724.84,-1263.5 h70
  text "4" at 8231.51,-1263.5 h70
  text "5" at 10730.5,-1263.5 h70
  text "6" at 13235.5,-1263.5 h70
M10 Fab Notes:
  drawing of 212 lines, arcs and shapes, not listed
  text "DESIGN INFORMATION" at 12381.02,6810 h60
  text "(REFER ALSO ARRAY/PANEL PROFILING INFORMATION)" at 12019.46,6648.29 h60
  text "BOARD SIZE" at 11333.46,6644 h60
  text "6500MIL" at 11795.78,6516.18 h60
  text "X" at 12301.46,6516.18 h60
  text "7000MIL" at 12532.78,6516.18 h60
  text "Number of Layers :" at 11736.46,6319 h60
  text "4" at 12831.27,6309 h60
  text "MIN. TRACK WIDTH:" at 11736.46,6180 h60
  text "8" at 12832.7,6180 h60
  text "MIL" at 12987.46,6180 h60
  text "MIN. CLEARANCE:" at 11736.46,6048 h60
  text "8" at 12832.7,6048 h60
  text "MIL" at 12987.46,6048 h60
  text "MIN. VIA PAD SIZE:" at 11736.46,5916 h60
  text "10" at 12802.71,5916 h60
  text "MIL" at 12987.46,5916 h60
  text "0.127mm (5MIL)" at 12431.46,5774.29 h60
  text "MINIMUM ANNULAR RING" at 11407.23,5770 h60
  text "EXTERNAL" at 13139.46,5770 h60
  text "PER" at 11607.23,5652 h60
  text "IPC-D-275 CLASS 2 LEVEL C" at 11827.23,5652 h60
  text "MIL, HOLES" at 13315.46,5539.71 h60
  text "+/-" at 12923,5539 h60
  text "+/-" at 13777,5539 h60
  text "REGISTRATION TOLERANCES:" at 11407.23,5534 h60
  text "METAL" at 12607,5534 h60
  text "5" at 13183.2,5534 h60
  text "3" at 14016.2,5534 h60
  text "MIL" at 14132.46,5534 h60
  text "MATERIAL:" at 11332.46,5324.54 h60
  text "FR-4 High Tg" at 12318.9,5184.21 h60
  text "FR-408" at 11753.46,5175.64 h60
  text "X" at 12165.46,5175.64 h60
  text "OTHER" at 13241.46,5175.64 h60
  text "62 MIL (1.6mm) +/-10%" at 12073.56,5012.92 h60
  text "THICKNESS:" at 11407.23,5008.64 h60
  text "X" at 11945.4,5008.64 h60
  text "OTHER" at 13358.46,5008.64 h60
  text "TOLERANCE:" at 11407.23,4850.64 h60
  text "X" at 12246.53,4850.64 h60
  text "ANSI IPC-6012 TYPE 3 CLASS 2" at 12433.48,4850.64 h60
  text "OTHER +/-" at 12433.46,4694.64 h60
  text "BOW & TWIST:" at 11407.23,4537.64 h60
  text "X" at 12246.53,4537.64 h60
  text "ANSI IPC-6012 TYPE 3 CLASS 2" at 12433.48,4537.64 h60
  text "OTHER +/-" at 12433.46,4379.13 h60
  text "COPPER THICKNESS (FINISHED):" at 11332.46,4243.64 h60
  text "1.4MIL (1oz)" at 12212.46,4090.92 h60
  text "2MIL (1.4oz)" at 12979.46,4090.92 h60
  text "2.8MIL (2oz)" at 13706.46,4090.92 h60
  text "OUTER:" at 11689.46,4086.64 h60
  text "X" at 13575,4087 h60
  text "1.4MIL (1oz)" at 12212.46,3933.92 h60
  text "2.8MIL (2oz)" at 12979.46,3933.92 h60
  text "N/A" at 13706,3934.29 h60
  text "INNER SIGNAL:" at 11400.38,3929.64 h60
  text "X" at 12085.42,3929.64 h60
  text "DRILLING:" at 11332.46,3790.64 h60
  text "REFERENCE:" at 11407.23,3673.64 h60
  text "X" at 12055.46,3673.64 h60
  text "AS SHOWN" at 12242.46,3673.64 h60
  text "X" at 12956.46,3673.64 h60
  text "NC_DRILL FILES" at 13093.46,3673.64 h60
  text "PTH MIN COPPER THICKNESS:" at 11407.23,3515.64 h60
  text "X" at 12757.46,3515.64 h60
  text "1MIL" at 12894.46,3515.64 h60
  text "OTHER" at 13391.46,3515.64 h60
  text "BOARD FINISH:" at 11332.46,3356.64 h60
  text "SILKSCREEN:" at 11487.68,3238.64 h60
  text "X" at 12436.46,3238.64 h60
  text "TOP" at 12562.46,3238.64 h60
  text "X" at 12946.46,3238.64 h60
  text "BOTTOM" at 13073.46,3238.64 h60
  text "SILKSCREEN COLOR:" at 11487.68,3071.64 h60
  text "X" at 12435.42,3071.64 h60
  text "WHITE" at 12562.46,3071.64 h60
  text "OTHER" at 13073.46,3071.64 h60
  text "SOLDER RESIST COLOR:" at 11487.68,2901.64 h60
  text "X" at 12055.42,2742.44 h60
  text "GREEN" at 12182.46,2742.44 h60
  text "BLUE" at 12773.46,2742.44 h60
  text "OTHER" at 13311.46,2742.44 h60
  text "IMMERSION GOLD (ENIG)" at 12393.46,2553.92 h60
  text "ENEPIG" at 13731,2550.64 h60
  text "SURFACE FINISH:" at 11332.46,2549.64 h60
  text "X" at 12206.51,2549.64 h60
  text "IMM. TIN/SILVER OR EQUIV" at 11662,2392.64 h60
  text "OTHER" at 13093.46,2392.64 h60
  text "ARRAY/PANEL:" at 11332.46,2213.64 h60
  text "CUT AND TRIM PER MECH LAYER 1" at 12393.46,2209.35 h60
  text "N.C. ROUTE" at 12393.46,2057.64 h60
  text "X" at 13072.46,2057.64 h60
  text "V. SCORE" at 13259.46,2057.64 h60
  text "CERTIFICATION:" at 11332.46,1920.64 h60
  text "MATERIALS AND WORKMANSHIP FOR ALL PCBS" at 12057.46,1920.64 h60
  text "TO MEET OR EXCEED THE REQUIREMENTS OF:" at 12057.46,1822.64 h60
  text "X" at 11683.96,1686.13 h60
  text "ANSI IPC-A-600F CLASS ->" at 11822.96,1686.13 h60
  text "X" at 13462.02,1686.13 h60
  text "2" at 13580.96,1686.14 h60
  text "1" at 13265.96,1684.64 h60
  text "3" at 13934.96,1684.64 h60
  text "X" at 11686.02,1526.64 h60
  text "UL 94V-0" at 11822.96,1526.64 h60
  text "X" at 12498.02,1526.64 h60
  text "RoHS" at 12634.96,1526.64 h60
  text "OTHER" at 13279.36,1526.64 h60
  text "PER ORDER" at 13676.42,1526.64 h60
  text "ADDITIONAL REQUIREMENTS:" at 11332.46,1385.64 h60
  text "MICROSECTION:" at 11407.23,1270.64 h60
  text "YES" at 12312.96,1270.64 h60
  text "REQUIRED" at 13174.46,1114.49 h60
  text "BARE BOARD ELEC. TEST:" at 11407.23,1111.64 h60
  text "NONE" at 12712.96,1111.64 h60
  text "X" at 13047.46,1111.64 h60
  text "PER ORDER" at 13766.46,1111.64 h60
  text "MANUFACTURER'S UL:" at 11407.23,954.64 h60
  text "RAIL" at 12572.96,950.35 h60
  text "METAL" at 13064.77,950.35 h60
  text "X" at 13440,950 h60
  text "SILK" at 13576.46,950.35 h60
  text ".Layer_Name" at 577,-858.49 h60
M11 Gerber Information:
  lines w10: -292,-930.17 6308,-930.17 ; -292,-726.83 6310,-726.83 ; -292,-523.5 -292,-1133.5 3713,-1133.5 6310,-1133.5 6310,-523.5 -291.5,-523.5 -291.5,-1133.5 1284,-1133.5 ; 2173,-1133.5 2173,-523.5 ; 3440,-726.83 3440,-523.5 ; 4280,-726.83 4280,-523.5 ; 4902,-1140 4902,-937.17
  text "ALL ARTWORK VIEWED FROM TOP SIDE" at -228.5,-655.67 h60
  text "BOARD #:" at 2248,-655.67 h60
  text ".PRJ_Number" at 2793.5,-655.67 h60
  text "REV:" at 3875,-655.67 h60
  text ".PCB_Rev" at 4166.5,-655.67 h60
  text "SVN REV:" at 4476,-655.67 h60
  text ".VersionControl_RevNumber" at 4982,-655.67 h60
  text "LAYER NAME =" at -228.5,-858.49 h60
  text "PLOT NAME =" at -228.5,-1064.34 h60
  text ".plot_File_Name" at 577,-1064.34 h60
  text "GENERATED    :" at 2250,-1064.34 h60
  text ".Print_Date" at 3119.5,-1064.34 h60
  text ".Print_Time" at 3848.5,-1064.34 h60
  text "TEXAS INSTRUMENTS" at 5113,-1064.34 h60
M12 Stackup:
  lines w6: 11360,7460 13910,7460 ; 11360,7564.4 13910,7564.4 ; 11300,6975 ccw(c11334,6975) 11334,6941 13936,6941 ccw(c13936,6975) 13970,6975 13970,7681 ccw(c13936,7681) 13936,7715 11334,7715 ccw(c11334,7681) 11300,7681 11300,6975
  text "The Stackup Legend below this is static." at 11605.5,7874.5 h60
  text "If you change the stackup, update the Legend." at 11615.5,7784.5 h60
  text "Layer Stack Up Detail for: Ref_Design.PcbDoc" at 11360,7597.1 h57
  text "Layer" at 11360,7525.4 h24
  text "Gerber" at 12255.81,7525.4 h24
  text "Copper" at 12819.33,7525.4 h24
  text "Dielectric" at 13422.04,7525.4 h24
  text "Name" at 11360,7477.4 h24
  text "Document" at 12255.81,7477.4 h24
  text "Thickness" at 12819.33,7477.4 h24
  text "Material" at 13422.04,7477.4 h24
  text "Top Solder Mask" at 11360,7384.44 h34
  text "(.GTS)" at 12255.81,7384.44 h34
  text "Solder Resist" at 13422.04,7384.44 h34
  text "Top Layer" at 11360,7287.69 h34
  text "(.GTL)" at 12255.81,7287.69 h34
  text "1.4mil" at 12819.33,7287.69 h34
  text "FR-4" at 13422.04,7239.31 h34
  text "Bottom Layer" at 11360,7190.94 h34
  text "(.GBL)" at 12255.81,7190.94 h34
  text "1.4mil" at 12819.33,7190.94 h34
  text "Bottom Solder Mask" at 11360,7094.19 h34
  text "(.GBS)" at 12255.81,7094.19 h34
  text "Solder Resist" at 13422.04,7094.19 h34
  text ".Layer_Name" at 577,-858.49 h60
M13 Component Bodies Top:
  text ".Layer_Name" at 577,-858.49 h60
M14 Component Bodies Bottom:
  text ".Layer_Name" at 577,-858.49 h60
M15 Courtyards Top:
  text ".Layer_Name" at 577,-858.49 h60
M16 Courtyards Bottom:
  text ".Layer_Name" at 577,-858.49 h60
Drill Drawing:
  text ".legend" at 5940.5,-72.5 h60
  text "Drill Table" at 5965.5,-257.5 h60
  text ".Layer_Name" at 577,-858.49 h60

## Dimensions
0,0 to 0,6500 on M2 Board Dimensions
0,0 to 7000,0 on M2 Board Dimensions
